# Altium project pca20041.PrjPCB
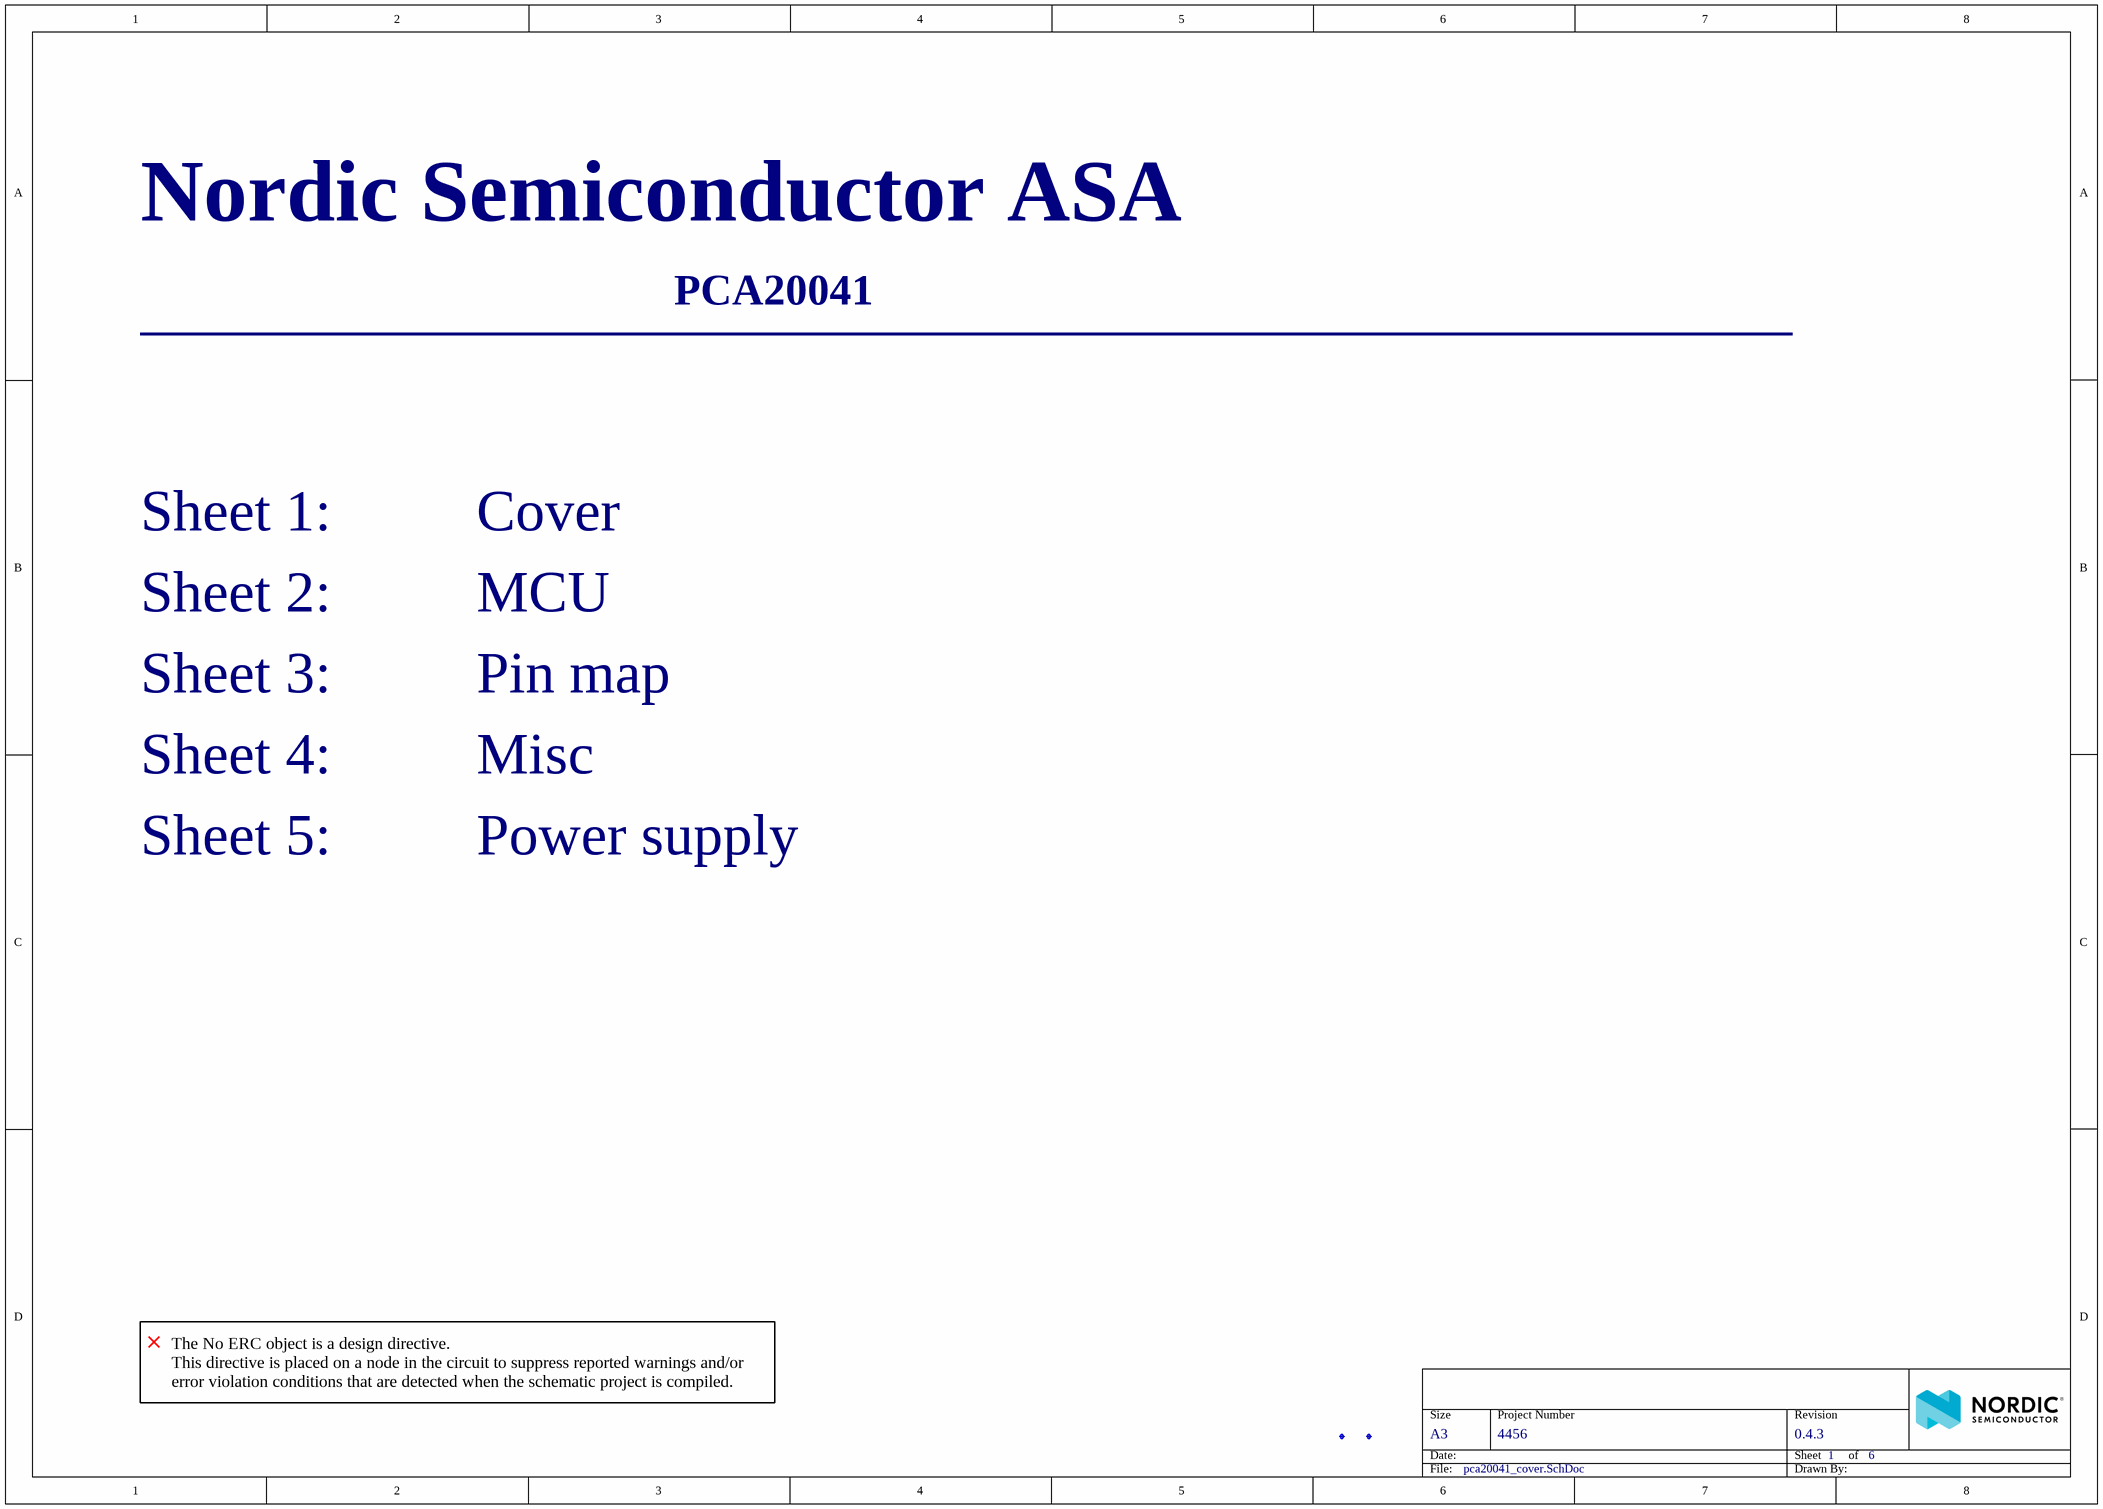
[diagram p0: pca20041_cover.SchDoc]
Author: RUBR/KJP/MASI; BoardThickness: 1.6mm; BoardTitle: nRF52840 Gaming Mouse; NrOfLayers: 4; Organization: Nordic Semiconductor; PCAName: PCA20041; PCBNumber: 400380; PCBRevision: 0012MASI; PCBStackup: 4001; ProjectName: nRF52 Desktop; ProjectNumber: 4456; Revision: 0.4.3; SilkscreenColor: White; SoldermaskColor: Blue; SurfaceFinish: ENIG
5 sheets, 122 parts. Net scope: flat (ports and power ports of the same name join across sheets).
Board file: 400380.PcbDoc
Sheets:
  pca20041_cover.SchDoc
  pca20041_mcu.SchDoc
  pca20041_pin_map.SchDoc
  pca20041_misc.SchDoc
  pca20041_power_supply.SchDoc

## Sheet pca20041_cover.SchDoc: =BoardTitle
size A3; Organization: Nordic Semiconductor; DocumentNumber: 1; Revision: 0.4.3; SheetNumber: 1; SheetTotal: 6; Author: RUBR/KJP/MASI; CompanyName: Nordic Semiconductor; DrawnBy: RUBR/KJP/MASI

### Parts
Fid1  Fiducial mark  [Fiducial]  (value not drawn)
Fid2  Fiducial mark  [Fiducial]  (value not drawn)

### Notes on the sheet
- Nordic Semiconductor ASA
- ________________________________________________________
- Sheet 1:          Cover
- Sheet 2:          MCU
- Sheet 3:          Pin map
- Sheet 4:          Misc
- Sheet 5:          Power supply
- The No ERC object is a design directive.
  This directive is placed on a node in the circuit to suppress reported warnings and/or error violation conditions that are detected when the schematic project is compiled.

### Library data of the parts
Fid1 Fid2 = Fid-Mark: Artikkelnr Noca: N.A.

## Sheet pca20041_mcu.SchDoc: =BoardTitle
size A3; Organization: Nordic Semiconductor; DocumentNumber: 2; Revision: 0.4.3; SheetNumber: 2; SheetTotal: 6; Author: RUBR/KJP/MASI; CompanyName: Nordic Semiconductor; DrawnBy: RUBR/KJP/MASI
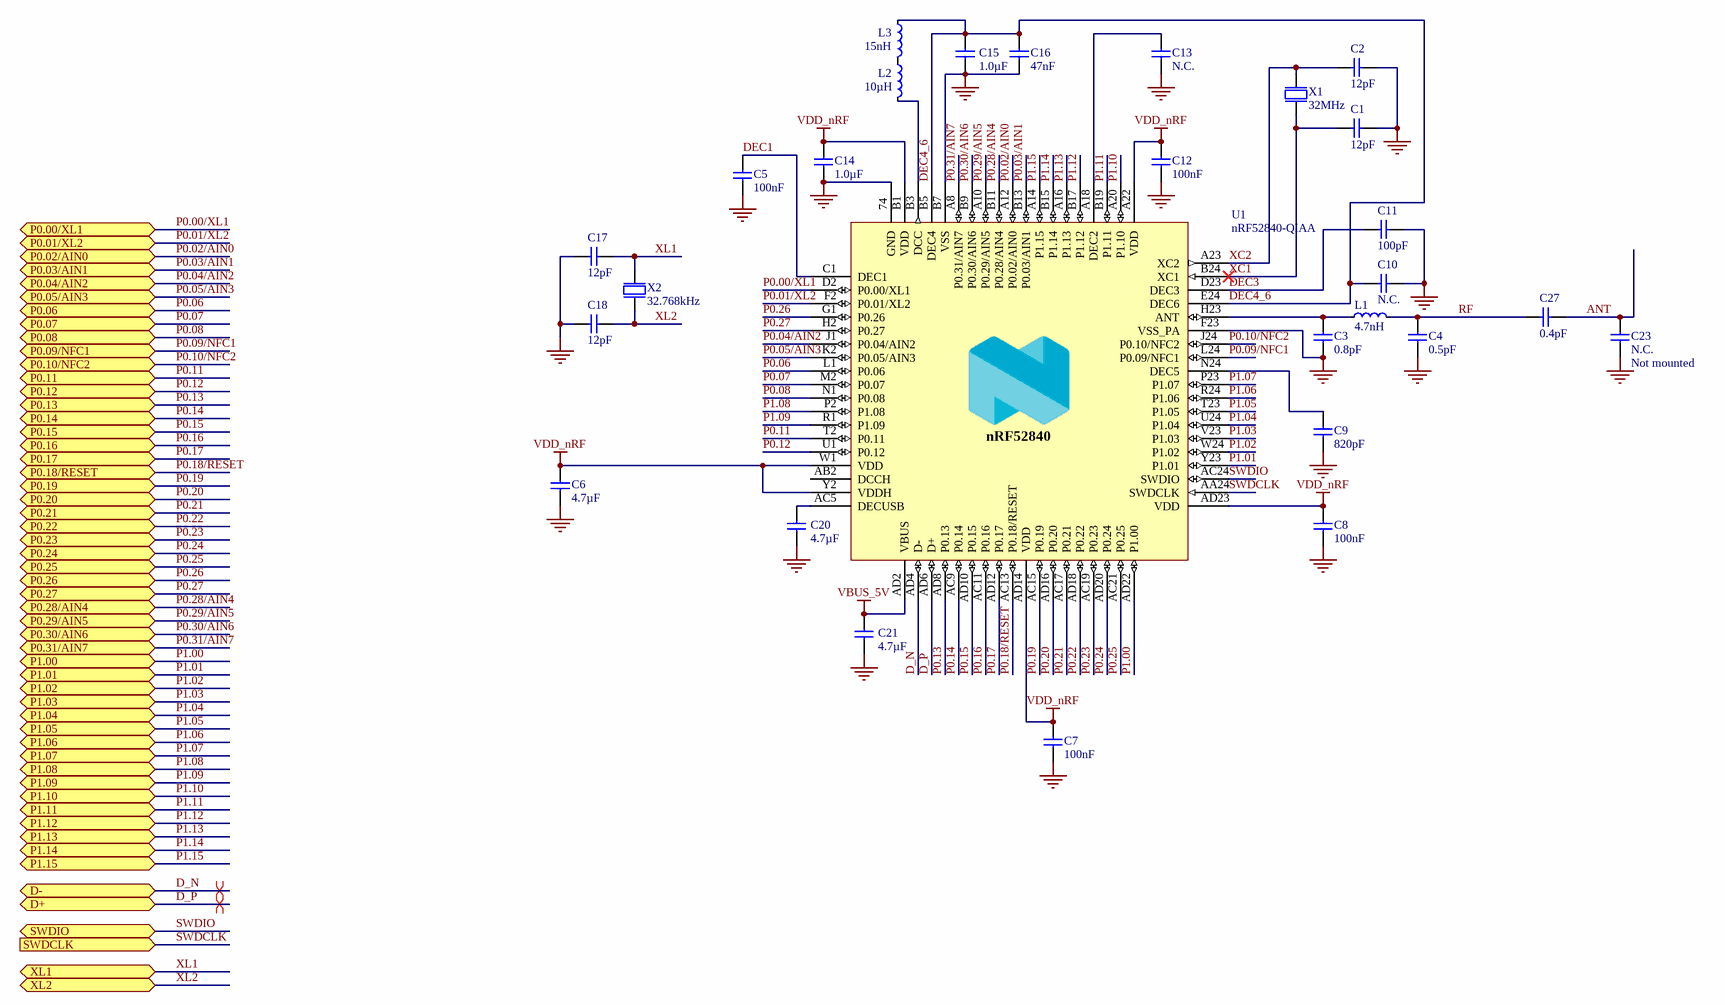
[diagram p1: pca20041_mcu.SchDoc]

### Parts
C1  12pF  [CAPC0603X03L_C]
C2  12pF  [CAPC0603X03L_C]
C3  0.8pF  [CAPC1005X04L]
C4  0.5pF  [CAPC1005X04L]
C5  100nF  [CAPC0603X03L_C]
C6  4.7µF  [CAPC1608X06L]
C7  100nF  [CAPC0603X03L_C]
C8  100nF  [CAPC0603X03L_C]
C9  820pF  [CAPC0603X03L_C]
C10  N.C.  [CAPC0603X03L_C]
C11  100pF  [CAPC0603X03L_C]
C12  100nF  [CAPC0603X03L_C]
C13  N.C.  [CAPC0603X03L_C]
C14  1.0µF  [CAPC1608X06L]
C15  1.0µF  [CAPC1608X06L]
C16  47nF  [CAPC0603X03L_C]
C17  12pF  [CAPC0603X03L_C]
C18  12pF  [CAPC0603X03L_C]
C20  4.7µF  [CAPC1608X06L]
C21  4.7µF  [CAPC1608X06L]
C23  N.C.  Assembly: Not mounted  [CAPC0603X03L_C]
C27  0.4pF  [CAPC0603X03L_C]
L1  4.7nH  [INDC1005X04L]
L2  10µH  [INDC1608X06L]
L3  15nH  [INDC1005X04L]
U1  nRF52840-QIAA  [AQFN50P700X700X85_HS-74N]
X1  32MHz  [BT-XTAL_2016]
X2  32.768kHz  [XTAL_2012]

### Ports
D+ (bidir), D- (bidir), P0.00/XL1 (bidir), P0.01/XL2 (bidir), P0.02/AIN0 (bidir), P0.03/AIN1 (bidir), P0.04/AIN2 (bidir), P0.05/AIN3 (bidir), P0.06 (bidir), P0.07 (bidir), P0.08 (bidir), P0.09/NFC1 (bidir), P0.10/NFC2 (bidir), P0.11 (bidir), P0.12 (bidir), P0.13 (bidir), P0.14 (bidir), P0.15 (bidir), P0.16 (bidir), P0.17 (bidir), P0.18/RESET (bidir), P0.19 (bidir), P0.20 (bidir), P0.21 (bidir), P0.22 (bidir), P0.23 (bidir), P0.24 (bidir), P0.25 (bidir), P0.26 (bidir), P0.27 (bidir), P0.28/AIN4 (bidir), P0.29/AIN5 (bidir), P0.30/AIN6 (bidir), P0.31/AIN7 (bidir), P1.00 (bidir), P1.01 (bidir), P1.02 (bidir), P1.03 (bidir), P1.04 (bidir), P1.05 (bidir), P1.06 (bidir), P1.07 (bidir), P1.08 (bidir), P1.09 (bidir), P1.10 (bidir), P1.11 (bidir), P1.12 (bidir), P1.13 (bidir), P1.14 (bidir), P1.15 (bidir), SWDCLK (in), SWDIO (bidir), XL1 (bidir), XL2 (bidir)

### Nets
GND: C1.2 C2.2 C3.1 C4.1 C5.2 C6.2 C7.2 C8.2 C9.2 C10.1 C11.2 C12.2 C13.2 C14.2 C15.1 C16.2 C17.2 C18.2 C20.2 C21.2 C23.2 U1.74(GND) U1.B7(VSS) U1.F23(VSS_PA) X1.2(GND) X1.4(GND)
VBUS_5V: C21.1 U1.AD2(VBUS)
VDD_nRF: C6.1 C7.1 C8.1 C12.1 C14.1 U1.A22(VDD) U1.AD14(VDD) U1.AD23(VDD) U1.B1(VDD) U1.W1(VDD) U1.Y2(VDDH)
ANT: C23.1 C27.2
D_N: U1.AD4(D-) ; port D-
D_P: U1.AD6(D+) ; port D+
DEC1: C5.1 U1.C1(DEC1)
DEC3: C11.1 U1.D23(DEC3)
DEC4_6: C10.2 C15.2 C16.1 L3.1 U1.B5(DEC4) U1.E24(DEC6)
P0.00/XL1: C17.1 U1.D2(P0.00/XL1) X2.1(inp) ; port P0.00/XL1, port XL1  [also labelled XL1]
P0.01/XL2: C18.1 U1.F2(P0.01/XL2) X2.2(out) ; port P0.01/XL2, port XL2  [also labelled XL2]
P0.02/AIN0: U1.A12(P0.02/AIN0) ; port P0.02/AIN0
P0.03/AIN1: U1.B13(P0.03/AIN1) ; port P0.03/AIN1
P0.04/AIN2: U1.J1(P0.04/AIN2) ; port P0.04/AIN2
P0.05/AIN3: U1.K2(P0.05/AIN3) ; port P0.05/AIN3
P0.06: U1.L1(P0.06) ; port P0.06
P0.07: U1.M2(P0.07) ; port P0.07
P0.08: U1.N1(P0.08) ; port P0.08
P0.09/NFC1: U1.L24(P0.09/NFC1) ; port P0.09/NFC1
P0.10/NFC2: U1.J24(P0.10/NFC2) ; port P0.10/NFC2
P0.11: U1.T2(P0.11) ; port P0.11
P0.12: U1.U1(P0.12) ; port P0.12
P0.13: U1.AD8(P0.13) ; port P0.13
P0.14: U1.AC9(P0.14) ; port P0.14
P0.15: U1.AD10(P0.15) ; port P0.15
P0.16: U1.AC11(P0.16) ; port P0.16
P0.17: U1.AD12(P0.17) ; port P0.17
P0.18/RESET: U1.AC13(P0.18/RESET) ; port P0.18/RESET
P0.19: U1.AC15(P0.19) ; port P0.19
P0.20: U1.AD16(P0.20) ; port P0.20
P0.21: U1.AC17(P0.21) ; port P0.21
P0.22: U1.AD18(P0.22) ; port P0.22
P0.23: U1.AC19(P0.23) ; port P0.23
P0.24: U1.AD20(P0.24) ; port P0.24
P0.25: U1.AC21(P0.25) ; port P0.25
P0.26: U1.G1(P0.26) ; port P0.26
P0.27: U1.H2(P0.27) ; port P0.27
P0.28/AIN4: U1.B11(P0.28/AIN4) ; port P0.28/AIN4
P0.29/AIN5: U1.A10(P0.29/AIN5) ; port P0.29/AIN5
P0.30/AIN6: U1.B9(P0.30/AIN6) ; port P0.30/AIN6
P0.31/AIN7: U1.A8(P0.31/AIN7) ; port P0.31/AIN7
P1.00: U1.AD22(P1.00) ; port P1.00
P1.01: U1.Y23(P1.01) ; port P1.01
P1.02: U1.W24(P1.02) ; port P1.02
P1.03: U1.V23(P1.03) ; port P1.03
P1.04: U1.U24(P1.04) ; port P1.04
P1.05: U1.T23(P1.05) ; port P1.05
P1.06: U1.R24(P1.06) ; port P1.06
P1.07: U1.P23(P1.07) ; port P1.07
P1.08: U1.P2(P1.08) ; port P1.08
P1.09: U1.R1(P1.09) ; port P1.09
P1.10: U1.A20(P1.10) ; port P1.10
P1.11: U1.B19(P1.11) ; port P1.11
P1.12: U1.B17(P1.12) ; port P1.12
P1.13: U1.A16(P1.13) ; port P1.13
P1.14: U1.B15(P1.14) ; port P1.14
P1.15: U1.A14(P1.15) ; port P1.15
RF: C4.2 C27.1 L1.2
SWDCLK: U1.AA24(SWDCLK) ; port SWDCLK
SWDIO: U1.AC24(SWDIO) ; port SWDIO
XC1: C1.1 U1.B24(XC1) X1.1(inp)
XC2: C2.1 U1.A23(XC2) X1.3(out)
NetC3_2: C3.2 L1.1 U1.H23(ANT)
NetC9_1: C9.1 U1.N24(DEC5)
NetC13_1: C13.1 U1.A18(DEC2)
NetC20_1: C20.1 U1.AC5(DECUSB)
NetL2_1: L2.1 L3.2
NetL2_2: L2.2 U1.B3(DCC)

Not connected (* = marked no-connect by the designer): U1 AB2(DCCH)

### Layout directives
differential pair: D_N, D_P

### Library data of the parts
C1 C2 C17 C18 = C0201-12p: Capacitor, NP0, ±2%; Part number IPS: 00000007848; Note: 25V; Artikkelnr Noca: N.A.
C3 = C0402-0.8p: Capacitor, NP0, ±5%; Part number IPS: 00000007782; Note: 50V; Artikkelnr Noca: 20029147
C4 = C0402-0.5p: Capacitor, NP0, ±0.05pF; Part number IPS: N.A.; Note: 50V; Artikkelnr Noca: 20020007
C5 C7 C8 C12 = C0201-100n: Capacitor, X5R, ±10%; Part number IPS: 00000001248; Note: 16V; Artikkelnr Noca: N.A.
C6 C20 = C0603-4µ7-6.3V-X7R: Capacitor, X7R, ±10%; Manufacturer: Samsung; Manufacturer Part Number: CL10B475KQ8NQNC; Part number IPS: N.A.; Note: 6.3V; Artikkelnr Noca: 20039473
C9 = C0201-820p: Capacitor, X7R, ±10%; Part number IPS: 00000001249; Note: 25V; Artikkelnr Noca: N.A.
C10 C13 = C0201-N.C.: Not mounted; Note: Chip Cap; Assembly: Not mounted; Artikkelnr Noca: N.A.
C11 = C0201-100p: Capacitor, NP0, ±2%; Part number IPS: 00000007853; Note: 25V; Artikkelnr Noca: N.A.
C14 C15 = C0603-1µ0: Capacitor, X7R, ±10%; Part number IPS: 00000000616; Note: 16V; Artikkelnr Noca: 20039282
C16 = C0201-47n: Capacitor, X5R, ±10%; Part number IPS: 00000001250; Note: 10V; Artikkelnr Noca: N.A.
C21 = C0603-4µ7-10V-X7S: Capacitor, X7S, ±10%; Part number IPS: N.A.; Note: 10V; Artikkelnr Noca: 20030013
C23 = C0201-N.C.: Not mounted; Note: Chip Cap; Artikkelnr Noca: N.A.
C27 = C0201-0.4p: Capacitor, NP0, ±0.05pF; Note: 50V; Artikkelnr Noca: N.A.
L1 = L0402-4n7: Inductor, 160mA, ±0.1nH; Manufacturer: Murata; Manufacturer Part Number: LQP15MN4N7B02D; Part number IPS: N.A.; Note: High frequency chip inductor ±5%; Artikkelnr Noca: 33029164
L2 = L0603-10µ: Inductor, 80mA, ±10%; Manufacturer: Taiyo Yuden; Manufacturer Part Number: LBMF1608T100K; Part number IPS: 00000007794; Note: LBMF1608T100K 10µH 80mA 0603; Artikkelnr Noca: 33029314
L3 = L0402-15n: Inductor, 320mA, ±5%; Manufacturer: Taiyo Yuden; Manufacturer Part Number: HK100515NJ-T; Part number IPS: 00000001262; Note: High frequency chip inductor ±10%; Artikkelnr Noca: 33029323
U1 = nRF52840-QIAAD0: Multi-protocol Bluetooth Low Energy, IEEE 802.15.4, ANT and 2.4GHz proprietary system-on-chip; Manufacturer: Nordic Semiconductor; Artikkelnr Noca: N.A.
X1 = XTAL_SMD2016_32MHz_8pF_General: XTAL SMD 2016, 32MHz, Cl=8pF, Total Tol: ±40ppm; Note: XTAL SMD 32.000MHz; Artikkelnr Noca: N.A.
X2 = XTAL_SMD2012_32.768kHz_9pF_NDK: XTAL SMD 2012, 32.768kHz, 9pF, ±20ppm; Manufacturer: NDK; Manufacturer Part Number: NX2012SA 32.768KHz  S1-4085-xx20-9; Note: XTAL SMD 32.768kHz; Artikkelnr Noca: N.A.

## Sheet pca20041_pin_map.SchDoc: =BoardTitle
size A3; Organization: Nordic Semiconductor; DocumentNumber: 3; Revision: 0.4.3; SheetNumber: 3; SheetTotal: 6; Author: RUBR/KJP/MASI; CompanyName: Nordic Semiconductor; DrawnBy: RUBR/KJP/MASI
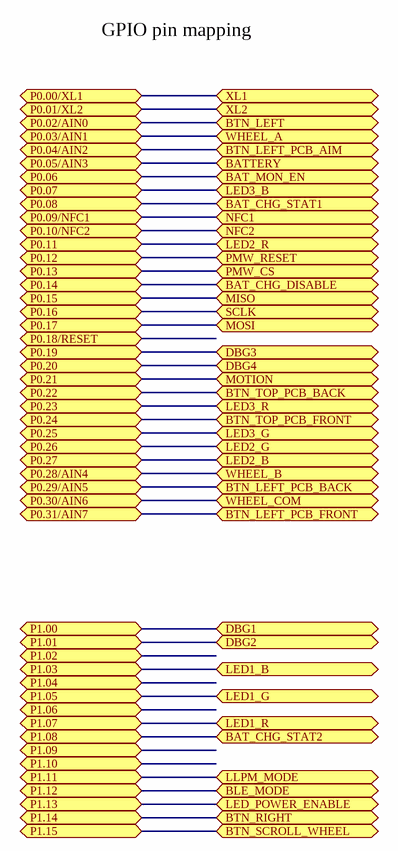
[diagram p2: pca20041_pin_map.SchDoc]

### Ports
BAT_CHG_DISABLE (bidir), BAT_CHG_STAT1 (bidir), BAT_CHG_STAT2 (bidir), BAT_MON_EN (bidir), BATTERY (bidir), BLE_MODE (bidir), BTN_LEFT (bidir), BTN_LEFT_PCB_AIM (bidir), BTN_LEFT_PCB_BACK (bidir), BTN_LEFT_PCB_FRONT (bidir), BTN_RIGHT (bidir), BTN_SCROLL_WHEEL (bidir), BTN_TOP_PCB_BACK (bidir), BTN_TOP_PCB_FRONT (bidir), DBG1 (bidir), DBG2 (bidir), DBG3 (bidir), DBG4 (bidir), LED1_B (bidir), LED1_G (bidir), LED1_R (bidir), LED2_B (bidir), LED2_G (bidir), LED2_R (bidir), LED3_B (bidir), LED3_G (bidir), LED3_R (bidir), LED_POWER_ENABLE (bidir), LLPM_MODE (bidir), MISO (bidir), MOSI (bidir), MOTION (bidir), NFC1 (bidir), NFC2 (bidir), P0.00/XL1 (bidir), P0.01/XL2 (bidir), P0.02/AIN0 (bidir), P0.03/AIN1 (bidir), P0.04/AIN2 (bidir), P0.05/AIN3 (bidir), P0.06 (bidir), P0.07 (bidir), P0.08 (bidir), P0.09/NFC1 (bidir), P0.10/NFC2 (bidir), P0.11 (bidir), P0.12 (bidir), P0.13 (bidir), P0.14 (bidir), P0.15 (bidir), P0.16 (bidir), P0.17 (bidir), P0.18/RESET (bidir), P0.19 (bidir), P0.20 (bidir), P0.21 (bidir), P0.22 (bidir), P0.23 (bidir), P0.24 (bidir), P0.25 (bidir), P0.26 (bidir), P0.27 (bidir), P0.28/AIN4 (bidir), P0.29/AIN5 (bidir), P0.30/AIN6 (bidir), P0.31/AIN7 (bidir), P1.00 (bidir), P1.01 (bidir), P1.02 (bidir), P1.03 (bidir), P1.04 (bidir), P1.05 (bidir), P1.06 (bidir), P1.07 (bidir), P1.08 (bidir), P1.09 (bidir), P1.10 (bidir), P1.11 (bidir), P1.12 (bidir), P1.13 (bidir), P1.14 (bidir), P1.15 (bidir), PMW_CS (bidir), PMW_RESET (bidir), SCLK (bidir), WHEEL_A (bidir), WHEEL_B (bidir), WHEEL_COM (bidir), XL1 (bidir), XL2 (bidir)

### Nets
P0.00/XL1: port XL1, port P0.00/XL1
P0.01/XL2: port XL2, port P0.01/XL2
P0.02/AIN0: port P0.02/AIN0, port BTN_LEFT
P0.03/AIN1: port P0.03/AIN1, port WHEEL_A
P0.04/AIN2: port P0.04/AIN2, port BTN_LEFT_PCB_AIM
P0.05/AIN3: port P0.05/AIN3, port BATTERY
P0.06: port P0.06, port BAT_MON_EN
P0.07: port P0.07, port LED3_B
P0.08: port P0.08, port BAT_CHG_STAT1
P0.09/NFC1: port P0.09/NFC1, port NFC1
P0.10/NFC2: port P0.10/NFC2, port NFC2
P0.11: port P0.11, port LED2_R
P0.12: port P0.12, port PMW_RESET
P0.13: port P0.13, port PMW_CS
P0.14: port P0.14, port BAT_CHG_DISABLE
P0.15: port P0.15, port MISO
P0.16: port P0.16, port SCLK
P0.17: port P0.17, port MOSI
P0.19: port P0.19, port DBG3
P0.20: port P0.20, port DBG4
P0.21: port P0.21, port MOTION
P0.22: port P0.22, port BTN_TOP_PCB_BACK
P0.23: port P0.23, port LED3_R
P0.24: port P0.24, port BTN_TOP_PCB_FRONT
P0.25: port P0.25, port LED3_G
P0.26: port P0.26, port LED2_G
P0.27: port P0.27, port LED2_B
P0.28/AIN4: port P0.28/AIN4, port WHEEL_B
P0.29/AIN5: port P0.29/AIN5, port BTN_LEFT_PCB_BACK
P0.30/AIN6: port P0.30/AIN6, port WHEEL_COM
P0.31/AIN7: port P0.31/AIN7, port BTN_LEFT_PCB_FRONT
P1.00: port P1.00, port DBG1
P1.01: port P1.01, port DBG2
P1.03: port P1.03, port LED1_B
P1.05: port P1.05, port LED1_G
P1.07: port P1.07, port LED1_R
P1.08: port P1.08, port BAT_CHG_STAT2
P1.11: port P1.11, port LLPM_MODE
P1.12: port P1.12, port BLE_MODE
P1.13: port P1.13, port LED_POWER_ENABLE
P1.14: port P1.14, port BTN_RIGHT
P1.15: port P1.15, port BTN_SCROLL_WHEEL

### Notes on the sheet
- GPIO pin mapping

## Sheet pca20041_misc.SchDoc: =BoardTitle
size A3; Organization: Nordic Semiconductor; DocumentNumber: 5; Revision: 0.4.3; SheetNumber: 5; SheetTotal: 6; Author: RUBR/KJP/MASI; CompanyName: Nordic Semiconductor; DrawnBy: RUBR/KJP/MASI
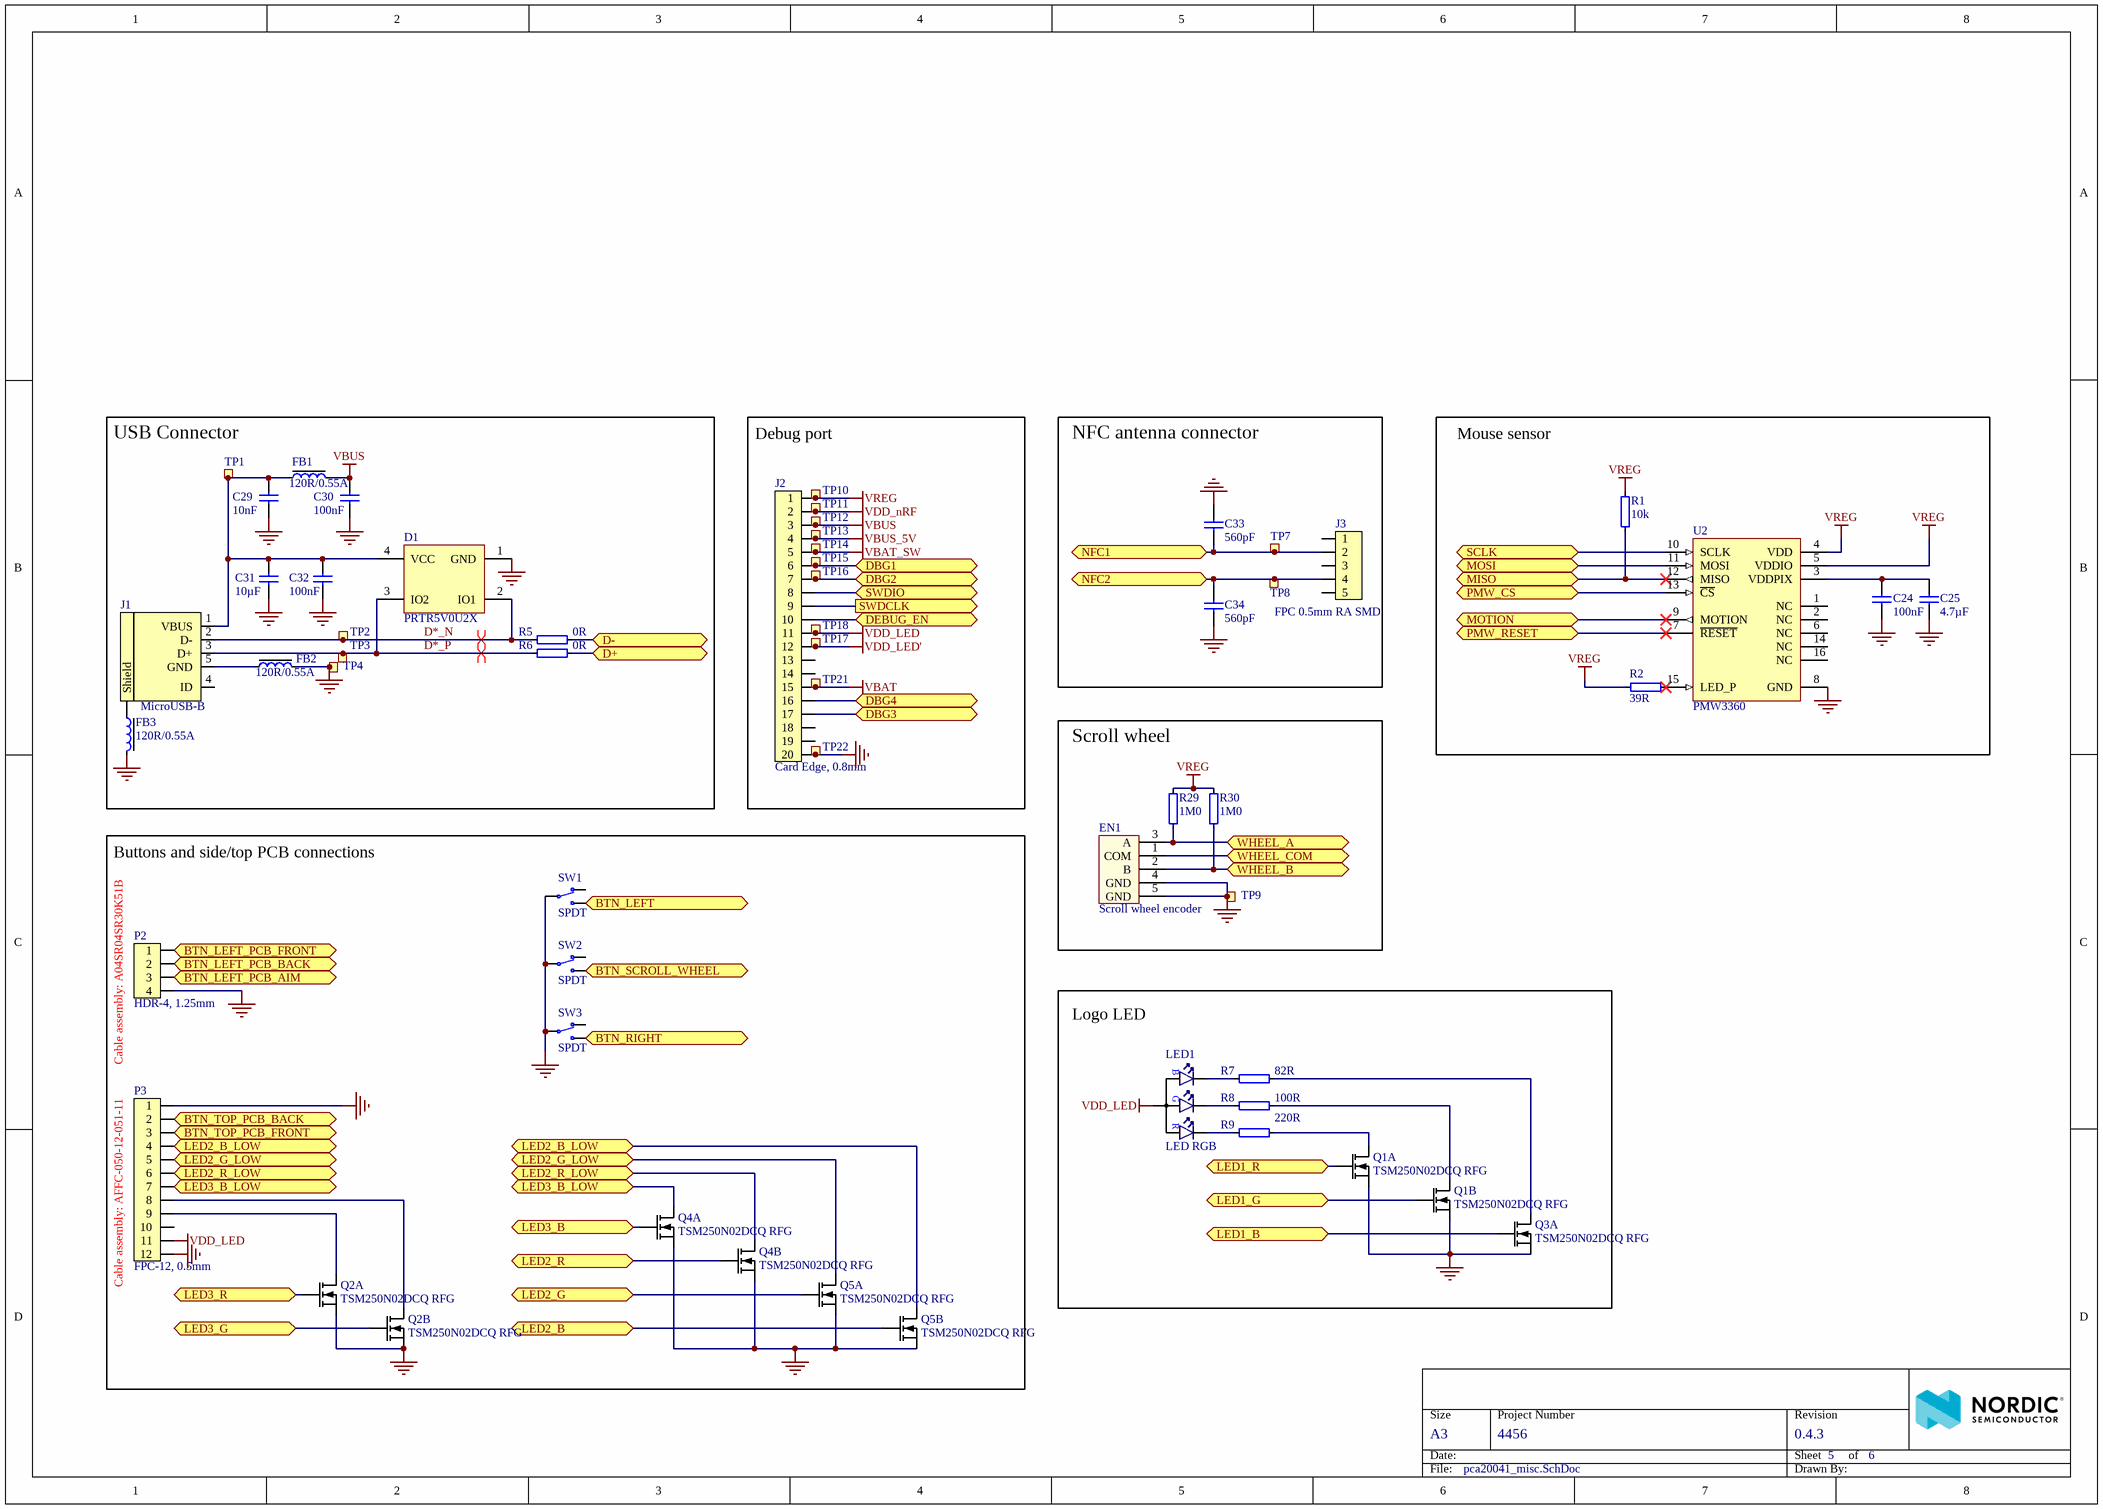
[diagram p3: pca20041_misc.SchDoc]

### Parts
C24  100nF  [CAPC1005X04L]
C25  4.7µF  [CAPC1608X06L]
C29  10nF  [CAPC1005X04L]
C30  100nF  [CAPC1005X04L]
C31  10µF  [CAPC1608X06L]
C32  100nF  [CAPC1005X04L]
C33  560pF  [CAPC1005X04L]
C34  560pF  [CAPC1005X04L]
D1  PRTR5V0U2X  [SOT190P230X110-4L]
EN1  Scroll wheel encoder  [M01_Scroll_Wheel_Encoder]
FB1  120R/0.55A  [INDC1005X04L]
FB2  120R/0.55A  [INDC1005X04L]
FB3  120R/0.55A  [INDC1005X04L]
J1  MicroUSB-B  [USB-Micro-B-RA-SMD-PiP]
J2  Card Edge, 0.8mm  [10056847-101LF]
J3  FPC 0.5mm RA SMD  [FPC_05P-0.5mm-RA-SMD]
LED1  LED RGB  [L1204_RGB_SIDE]
P2  HDR-4, 1.25mm  [1734598-4]
P3  FPC-12, 0.5mm  [10051922-1210ELF]
Q1  TSM250N02DCQ RFG  [DFN65P200X200X80_HS-6N]  (parts A,B of 2)
Q2  TSM250N02DCQ RFG  [DFN65P200X200X80_HS-6N]  (parts A,B of 2)
Q3  TSM250N02DCQ RFG  [DFN65P200X200X80_HS-6N]  (part A of 2)
Q4  TSM250N02DCQ RFG  [DFN65P200X200X80_HS-6N]  (parts A,B of 2)
Q5  TSM250N02DCQ RFG  [DFN65P200X200X80_HS-6N]  (parts A,B of 2)
R1  10k  [RESC0603X03L_C]
R2  39R  [RESC0603X03L_C]
R5  0R  [RESC0603X03L_C]
R6  0R  [RESC0603X03L_C]
R7  82R  [RESC0603X03L_C]
R8  100R  [RESC0603X03L_C]
R9  220R  [RESC0603X03L_C]
R29  1M0  [RESC0603X03L_C]
R30  1M0  [RESC0603X03L_C]
SW1  SPDT  [D2F-F]
SW2  SPDT  [D2F-F]
SW3  SPDT  [D2F-F]
TP1  Ø1.5mm,SMD  [TP_SMD_Ø1.5mm]  (value not drawn)  (no BOM)
TP2  Ø1.5mm,SMD  [TP_SMD_Ø1.5mm]  (value not drawn)  (no BOM)
TP3  Ø1.5mm,SMD  [TP_SMD_Ø1.5mm]  (value not drawn)  (no BOM)
TP4  Ø1.5mm,SMD  [TP_SMD_Ø1.5mm]  (value not drawn)  (no BOM)
TP7  Ø1.5mm,SMD  [TP_SMD_Ø1.5mm]  (value not drawn)  (no BOM)
TP8  Ø1.5mm,SMD  [TP_SMD_Ø1.5mm]  (value not drawn)  (no BOM)
TP9  TP  [TESTPAD-TH]  (value not drawn)  (no BOM)
TP10  Ø1.5mm,SMD  [TP_SMD_Ø1.5mm]  (value not drawn)  (no BOM)
TP11  Ø1.5mm,SMD  [TP_SMD_Ø1.5mm]  (value not drawn)  (no BOM)
TP12  Ø1.5mm,SMD  [TP_SMD_Ø1.5mm]  (value not drawn)  (no BOM)
TP13  Ø1.5mm,SMD  [TP_SMD_Ø1.5mm]  (value not drawn)  (no BOM)
TP14  Ø1.5mm,SMD  [TP_SMD_Ø1.5mm]  (value not drawn)  (no BOM)
TP15  Ø1.5mm,SMD  [TP_SMD_Ø1.5mm]  (value not drawn)  (no BOM)
TP16  Ø1.5mm,SMD  [TP_SMD_Ø1.5mm]  (value not drawn)  (no BOM)
TP17  Ø1.5mm,SMD  [TP_SMD_Ø1.5mm]  (value not drawn)  (no BOM)
TP18  Ø1.5mm,SMD  [TP_SMD_Ø1.5mm]  (value not drawn)  (no BOM)
TP21  Ø1.5mm,SMD  [TP_SMD_Ø1.5mm]  (value not drawn)  (no BOM)
TP22  Ø1.5mm,SMD  [TP_SMD_Ø1.5mm]  (value not drawn)  (no BOM)
U2  PMW3360  [PMW3360DM-T2QU]

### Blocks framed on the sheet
USB Connector: C29-C32 D1 FB1-FB3 J1 R5 R6 TP1-TP4
Debug port: J2 TP10-TP18 TP21 TP22
NFC antenna connector: C33 C34 J3 TP7 TP8
Mouse sensor: C24 C25 R1 R2 U2
Scroll wheel: EN1 R29 R30 TP9
Buttons and side/top PCB connections: P2 P3 Q2 Q4 Q5 SW1-SW3
Logo LED: LED1 Q1 Q3 R7-R9

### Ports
BTN_LEFT (bidir), BTN_LEFT_PCB_AIM (bidir), BTN_LEFT_PCB_BACK (bidir), BTN_LEFT_PCB_FRONT (bidir), BTN_RIGHT (bidir), BTN_SCROLL_WHEEL (bidir), BTN_TOP_PCB_BACK (bidir), BTN_TOP_PCB_FRONT (bidir), D+ (bidir), D- (bidir), DBG1 (bidir), DBG2 (bidir), DBG3 (bidir), DBG4 (bidir), DEBUG_EN (bidir), LED1_B (bidir), LED1_G (bidir), LED1_R (bidir), LED2_B (bidir), LED2_B_LOW (bidir), LED2_G (bidir), LED2_G_LOW (bidir), LED2_R (bidir), LED2_R_LOW (bidir), LED3_B (bidir), LED3_B_LOW (bidir), LED3_G (bidir), LED3_R (bidir), MISO (bidir), MOSI (bidir), MOTION (bidir), NFC1 (bidir), NFC2 (bidir), PMW_CS (bidir), PMW_RESET (bidir), SCLK (bidir), SWDCLK (out), SWDIO (bidir), WHEEL_A (bidir), WHEEL_B (bidir), WHEEL_COM (bidir)

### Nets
GND: C24.1 C25.1 C29.1 C30.1 C31.1 C32.1 C33.2 C34.1 D1.1(GND) EN1.4(GND) EN1.5(GND) FB2.2 FB3.2 J2.20 P2.4 P3.1 P3.12 Q1.1(S1) Q1.4(S2) Q2.1(S1) Q2.4(S2) Q3.1(S1) Q4.1(S1) Q4.4(S2) Q5.1(S1) Q5.4(S2) SW1.2(COM) SW2.2(COM) SW3.2(COM) TP4.1 TP9.1 TP22.1 U2.8(GND)
VBAT: J2.15 TP21.1
VBAT_SW: J2.5 TP14.1
VBUS: C30.2 FB1.2 J2.3 TP12.1
VBUS_5V: J2.4 TP13.1
VDD_LED: J2.11 LED1.4(A) P3.11 TP18.1
VDD_LED': J2.12 TP17.1
VDD_nRF: J2.2 TP11.1
VREG: J2.1 R1.2 R2.2 R29.2 R30.2 TP10.1 U2.4(VDD) U2.5(VDDIO)
D*_N: D1.2(IO1) J1.2(D-) R5.2 TP2.1
D*_P: D1.3(IO2) J1.3(D+) R6.2 TP3.1
D_N: R5.1 ; port D-
D_P: R6.1 ; port D+
EN: J2.10 ; port DEBUG_EN
LED2_B_LOW: P3.4 Q5.3(D2) ; port LED2_B_LOW
LED2_G_LOW: P3.5 Q5.6(D1) ; port LED2_G_LOW
LED2_R_LOW: P3.6 Q4.3(D2) ; port LED2_R_LOW
LED3_B_LOW: P3.7 Q4.6(D1) ; port LED3_B_LOW
P0.02/AIN0: SW1.3(N.O) ; port BTN_LEFT
P0.03/AIN1: EN1.3(A) R29.1 ; port WHEEL_A
P0.04/AIN2: P2.3 ; port BTN_LEFT_PCB_AIM
P0.07: Q4.2(G1) ; port LED3_B
P0.09/NFC1: C33.1 J3.2 TP7.1 ; port NFC1
P0.10/NFC2: C34.2 J3.4 TP8.1 ; port NFC2
P0.11: Q4.5(G2) ; port LED2_R
P0.12: U2.7(~{RESET}) ; port PMW_RESET
P0.13: U2.13(~{CS}) ; port PMW_CS
P0.15: R1.1 U2.12(MISO) ; port MISO
P0.16: U2.10(SCLK) ; port SCLK
P0.17: U2.11(MOSI) ; port MOSI
P0.19: J2.17 ; port DBG3
P0.20: J2.16 ; port DBG4
P0.21: U2.9(MOTION) ; port MOTION
P0.22: P3.2 ; port BTN_TOP_PCB_BACK
P0.23: Q2.2(G1) ; port LED3_R
P0.24: P3.3 ; port BTN_TOP_PCB_FRONT
P0.25: Q2.5(G2) ; port LED3_G
P0.26: Q5.2(G1) ; port LED2_G
P0.27: Q5.5(G2) ; port LED2_B
P0.28/AIN4: EN1.2(B) R30.1 ; port WHEEL_B
P0.29/AIN5: P2.2 ; port BTN_LEFT_PCB_BACK
P0.30/AIN6: EN1.1(COM) ; port WHEEL_COM
P0.31/AIN7: P2.1 ; port BTN_LEFT_PCB_FRONT
P1.00: J2.6 TP15.1 ; port DBG1
P1.01: J2.7 TP16.1 ; port DBG2
P1.03: Q3.2(G1) ; port LED1_B
P1.05: Q1.5(G2) ; port LED1_G
P1.07: Q1.2(G1) ; port LED1_R
P1.14: SW3.3(N.O) ; port BTN_RIGHT
P1.15: SW2.3(N.O) ; port BTN_SCROLL_WHEEL
SWDCLK: J2.9 ; port SWDCLK
SWDIO: J2.8 ; port SWDIO
NetC24_2: C24.2 C25.2 U2.3(VDDPIX)
NetC29_2: C29.2 C31.2 C32.2 D1.4(VCC) FB1.1 J1.1(VBUS) TP1.1
NetFB2_1: FB2.1 J1.5(GND)
NetFB3_1: FB3.1 J1.6(Shield)
NetLED1_1: LED1.1(C_RED) R9.2
NetLED1_2: LED1.2(C_GREEN) R8.2
NetLED1_3: LED1.3(C_BLUE) R7.2
NetP3_8: P3.8 Q2.3(D2)
NetP3_9: P3.9 Q2.6(D1)
NetQ1_3: Q1.3(D2) R8.1
NetQ1_6: Q1.6(D1) R9.1
NetQ3_6: Q3.6(D1) R7.1
NetR2_1: R2.1 U2.15(LED_P)

Not connected (* = marked no-connect by the designer): J1 4(ID); J2 13 14 18 19; J3 1 3 5; P3 10; SW1 1(N.C); SW2 1(N.C); SW3 1(N.C); U2 1(NC) 2(NC) 6(NC) 14(NC) 16(NC)

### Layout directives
differential pair: D*_N, D*_P

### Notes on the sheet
- Cable assembly: A04SR04SR30K51B
- (near P3) Cable assembly: AFFC-050-12-051-11

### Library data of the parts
C24 C30 C32 = C0402-100n: Capacitor, X7R, ±10%; Part number IPS: 00000005296; Note: 16V; Artikkelnr Noca: 20039200
C25 = C0603-4µ7: Capacitor, X5R, ±10%; Part number IPS: 00000007783; Note: 6.3V; Artikkelnr Noca: 20069060
C29 = C0402-10n: Capacitor, X7R, ±10%; Part number IPS: 00000007784; Note: 16V; Artikkelnr Noca: 20039166
C31 = C0603-10µ: Capacitor, X5R, ±20%; Part number IPS: 00000007785; Note: 6.3V; Artikkelnr Noca: 20039234
C33 C34 = C0402-560p: Capacitor, NP0, ±5%; Part number IPS: N.A.; Note: 50V; Artikkelnr Noca: 20029161
D1 = PRTR5V0U2X: Ultra low capacitance double rail-to-rail ESD protection diode; Manufacturer: NXP; Part number IPS: 00000009951; Artikkelnr Noca: 10069015
EN1 = M01_Scroll_wheel_encoder, 10.5mm: Scroll wheel encoder, 10.5mm; Artikkelnr Noca: N.A.
FB1-FB3 = FB0402-120R@100M-500mA: Ferrite Bead, 120 Ohm @ 100MHz, 500mA, 250 mOhm Max; Manufacturer: Murata; Manufacturer Part Number: BLM15AG121SN1D; Part number IPS: N.A.; Note: Chip EMIFIL Inductor Type Chip Ferrite Bead; Artikkelnr Noca: 33029317
J1 = USB-Micro-B-RA-SMD-PiP: MicroUSB-B-SMT; Manufacturer: Allen Creations Corp.; Manufacturer Part Number: AJU55-BS2111-L; Part number IPS: 00000007790; Artikkelnr Noca: 55029020
J2 = 10056847-101LF: 0.8mm pitch, dual edge, right angle, SMD, card edge connector; Manufacturer: FCI; Artikkelnr Noca: N.A.
J3 = FPC_05P-0.5mm-RA-SMD: 0.5mm FPC, 5P,Right Angle SMT,Double Contact,H=1.2mm,White, Tin plated; Manufacturer: W-CON; Manufacturer Part Number: 5141-05RZDNWR01; Part number IPS: 00000007792; Artikkelnr Noca: 55010020
LED1 = Led_RGB_Side: Optek, Side mounted RGB 1204 SMD LED; Manufacturer Part Number: OVSRRGBCC3; Artikkelnr Noca: N.A.
P2 = 1734598-4: Connector Header Through Hole 4 position 0.049" (1.25mm); Manufacturer: TE Connectivity; Artikkelnr Noca: N.A.
P3 = 10051922-1210ELF: 0.5mm pitch, bottom side contact, side entry SMD FPC connector; Manufacturer: FCI; Artikkelnr Noca: N.A.
Q1-Q5 = TSM250N02DCQ RFG: Dual N Ch MOFET, 5.8A, 55mOhm max, 620mW; Manufacturer: Taiwan Semiconductor; Artikkelnr Noca: N.A.
R1 = R0201-10k: Resistor, ±1%, 0.05W; Part number IPS: 00000001255; Note: Chip Res 1%; Artikkelnr Noca: N.A.
R2 = R0201-39R: Resistor, ±1%, 0.05W; Note: Chip Res 1%; Artikkelnr Noca: N.A.
R5 R6 = R0201-0R: Resistor, ±5%, 0.05W; Part number IPS: 00000003245; Note: Chip Res 5%; Artikkelnr Noca: N.A.
R7 = R0201-82R: Resistor, ±1%, 0.05W; Note: Chip Res 1%; Artikkelnr Noca: N.A.
R8 = R0201-100: Resistor, ±1%, 0.05W; Note: Chip Res 1%; Artikkelnr Noca: N.A.
R9 = R0201-220: Resistor, ±1%, 0.05W; Part number IPS: 00000000863; Note: Chip Res 1%; Artikkelnr Noca: N.A.
R29 R30 = R0201-1M0: Resistor, ±1%, 0.05W; Note: Chip Res 1%; Artikkelnr Noca: N.A.
SW1-SW3 = D2F-F: SWITCH SNAP ACTION SPDT 1A 125V; Manufacturer: Omron; Artikkelnr Noca: N.A.
TP1-TP4 TP7 TP8 TP10-TP18 TP21 TP22 = TP_SMD_Ø1.5MM: 1.0mm circular SMD testpad; Manufacturer: Nordic Semiconductor; Artikkelnr Noca: N.A.
TP9 = Testpoint TH: Testpoint, through hole; Artikkelnr Noca: N.A.
U2 = PMW3360DM-T2QU: Optical Gaming Navigation Sensor; Manufacturer: PixArt; Artikkelnr Noca: N.A.

## Sheet pca20041_power_supply.SchDoc: =BoardTitle
size A3; Organization: Nordic Semiconductor; DocumentNumber: 6; Revision: 0.4.3; SheetNumber: 6; SheetTotal: 6; Author: RUBR/KJP/MASI; CompanyName: Nordic Semiconductor; DrawnBy: RUBR/KJP/MASI
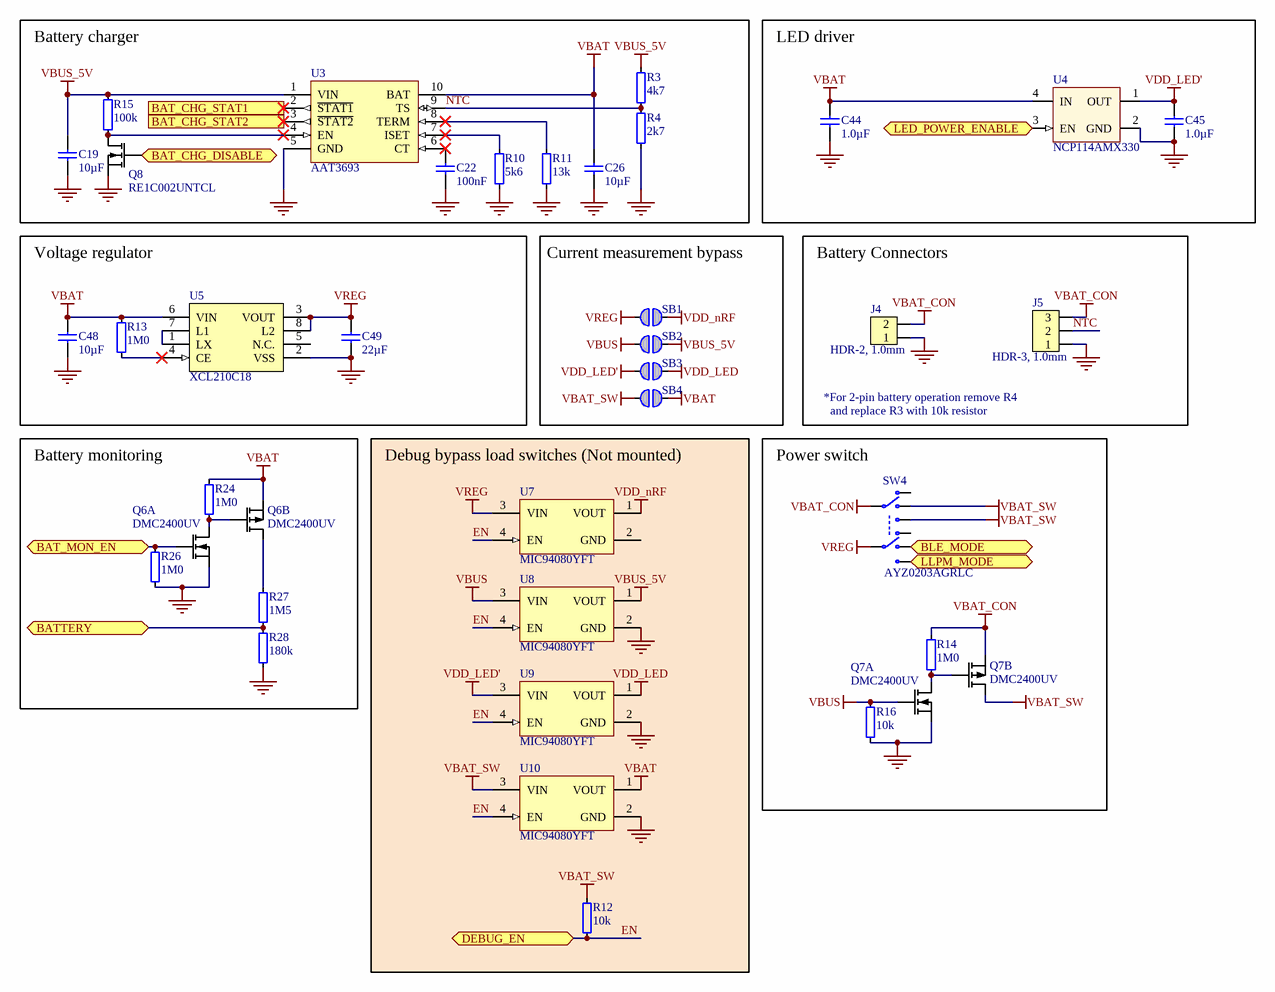
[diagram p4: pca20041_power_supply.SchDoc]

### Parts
C19  10µF  [CAPC1608X06L]
C22  100nF  [CAPC0603X03L_C]
C26  10µF  [CAPC1608X06L]
C44  1.0µF  [CAPC1005X04L]
C45  1.0µF  [CAPC1005X04L]
C48  10µF  [CAPC1608X06L]
C49  22µF  [CAPC1608X06L]
J4  HDR-2, 1.0mm  [BM02B-SRSS-TB]
J5  HDR-3, 1.0mm  [BM03B-SRSS-TB]
Q6  DMC2400UV  [SOTFL50P162X60-6N]  (parts A,B of 2)
Q7  DMC2400UV  [SOTFL50P162X60-6N]  (parts A,B of 2)
Q8  RE1C002UNTCL  [SOTFL50P160X78-3N]
R3  4k7  [RESC0603X03L_C]
R4  2k7  [RESC0603X03L_C]
R10  5k6  [RESC0603X03L_C]
R11  13k  [RESC0603X03L_C]
R12  10k  [RESC1005X04L]
R13  1M0  [RESC1005X04L]
R14  1M0  [RESC0603X03L_C]
R15  100k  [RESC0603X03L_C]
R16  10k  [RESC0603X03L_C]
R24  1M0  [RESC0603X03L_C]
R26  1M0  [RESC0603X03L_C]
R27  1M5  [RESC0603X03L_C]
R28  180k  [RESC0603X03L_C]
SB1  Solderbridge  [Solderbridge]  (value not drawn)  (no BOM)
SB2  Solderbridge  [Solderbridge]  (value not drawn)  (no BOM)
SB3  Solderbridge  [Solderbridge]  (value not drawn)  (no BOM)
SB4  Solderbridge  [Solderbridge]  (value not drawn)  (no BOM)
SW4  AYZ0203AGRLC  [AYZ0203AGRLC]
U3  AAT3693  [QFN40P220X220X80_HS-11N]
U4  NCP114AMX330  [UDFN65P100X100X60_HS-5N]
U5  XCL210C18  [CL-2025]
U7  MIC94080YFT  [TMLF40P85X85X60-4N]
U8  MIC94080YFT  [TMLF40P85X85X60-4N]
U9  MIC94080YFT  [TMLF40P85X85X60-4N]
U10  MIC94080YFT  [TMLF40P85X85X60-4N]

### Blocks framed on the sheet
Battery charger: C19 C22 C26 Q8 R3 R4 R10 R11 R15 U3
LED driver: C44 C45 U4
Voltage regulator: C48 C49 R13 U5
Current measurement bypass: SB1-SB4
Battery Connectors: J4 J5
Battery monitoring: Q6 R24 R26-R28
Debug bypass load switches (Not mounted): R12 U7-U10
Power switch: Q7 R14 R16 SW4

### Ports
BAT_CHG_DISABLE (bidir), BAT_CHG_STAT1 (out), BAT_CHG_STAT2 (out), BAT_MON_EN (bidir), BATTERY (bidir), BLE_MODE (bidir), DEBUG_EN (bidir), LED_POWER_ENABLE (bidir), LLPM_MODE (bidir)

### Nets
GND: C19.1 C22.2 C26.1 C44.2 C45.2 C48.1 C49.1 J4.1 J5.1 Q6.1(S1) Q7.1(S1) Q8.2(S) R4.1 R10.1 R11.1 R16.1 R26.2 R28.2 U3.5(GND) U3.11(GND) U4.2(GND) U4.5(EPAD) U5.2(VSS) U5.9(VSS) U7.2(GND) U8.2(GND) U9.2(GND) U10.2(GND)
VBAT: C26.2 C44.1 C48.2 Q6.4(S2) R13.2 R24.1 SB4.2 U3.10(BAT) U4.4(IN) U5.6(VIN) U10.1(VOUT)
VBAT_CON: J4.2 J5.3 Q7.4(S2) R14.2 SW4.3(COM-1)
VBAT_SW: Q7.3(D2) R12.2 SB4.1 SW4.2(N.O-1) SW4.4(COM-1) U10.3(VIN)
VBUS: Q7.2(G1) R16.2 SB2.1 U8.3(VIN)
VBUS_5V: C19.2 R3.2 R15.2 SB2.2 U3.1(VIN) U8.1(VOUT)
VDD_LED: SB3.2 U9.1(VOUT)
VDD_LED': C45.1 SB3.1 U4.1(OUT) U9.3(VIN)
VDD_nRF: SB1.2 U7.1(VOUT)
VREG: C49.2 SB1.1 SW4.7(COM-2) U5.3(VOUT) U5.8(L2) U7.3(VIN)
EN: R12.1 U7.4(EN) U8.4(EN) U9.4(EN) U10.4(EN) ; port DEBUG_EN
NTC: J5.2 R3.1 R4.2 U3.9(TS)
P0.05/AIN3: R27.2 R28.1 ; port BATTERY
P0.06: Q6.2(G1) R26.1 ; port BAT_MON_EN
P0.08: U3.2(~{STAT1}) ; port BAT_CHG_STAT1
P0.14: Q8.1(G) ; port BAT_CHG_DISABLE
P1.08: U3.3(~{STAT2}) ; port BAT_CHG_STAT2
P1.11: SW4.8(COM-2) ; port LLPM_MODE
P1.12: SW4.6(N.O-2) ; port BLE_MODE
P1.13: U4.3(EN) ; port LED_POWER_ENABLE
NetC22_1: C22.1 U3.6(CT)
NetQ6_3: Q6.3(D2) R27.1
NetQ6_5: Q6.5(G2) Q6.6(D1) R24.2
NetQ7_5: Q7.5(G2) Q7.6(D1) R14.1
NetQ8_3: Q8.3(D) R15.1 U3.4(EN)
NetR10_2: R10.2 U3.7(ISET)
NetR11_2: R11.2 U3.8(TERM)
NetR13_1: R13.1 U5.4(CE)
NetU5_1: U5.1(LX) U5.7(L1)

Not connected (* = marked no-connect by the designer): SW4 1(N.C-1) 5(N.C-2); U5 5(N.C.)

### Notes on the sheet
- *For 2-pin battery operation remove R4
- and replace R3 with 10k resistor

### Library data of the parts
C19 C26 = C0603-10µF-25V: Capacitor, 0603, 25V, X5R; Part number IPS: N.A.; Artikkelnr Noca: 20039436
C22 = C0201-100n: as C5 on sheet pca20041_mcu
C44 C45 = C0402-1µ0: Capacitor, X5R, ±5%; Part number IPS: 00000007786; Note: 6.3V; Artikkelnr Noca: 20039235
C48 = C0603-10µ: as C31 on sheet pca20041_misc
C49 = C0603-22µ-6.3V: CAP CER 22UF 6.3V 20% X5R 0603; Manufacturer: Samsung; Manufacturer Part Number: CL10A226MQ8NRNC; Part number IPS: 00000007787; Artikkelnr Noca: N.A.
J4 = BM02B-SRSS-TB: 1.0mm pitch top entry SMD wire to board connector; Manufacturer: JST; Note: JST, Header; Artikkelnr Noca: N.A.
J5 = BM03B-SRSS-TB: 1.0mm pitch top entry SMD wire to board connector; Manufacturer: JST; Note: JST, Header; Artikkelnr Noca: N.A.
Q6 Q7 = DMC2400UV: Dual N & P Ch MOFET, 1.03A/0.7A, 480mOhm, 450mW; Manufacturer: Diodes Incorporated; Part number IPS: 00000007803; Note: Dual N & P Channel Digital FET; Artikkelnr Noca: N.A.
Q8 = RE1C002UNTCL: MOSFET N-CH 20V 0.2A EMT3; Manufacturer: Rohm Semiconductor; Artikkelnr Noca: N.A.
R3 = R0201-4k7: Resistor, ±1%, 0.05W; Note: Chip Res 1%; Artikkelnr Noca: N.A.
R4 = R0201-2k7: Resistor, ±1%, 0.05W; Note: Chip Res 1%; Artikkelnr Noca: N.A.
R10 = R0201-5k6: Resistor, ±1%, 0.05W; Note: Chip Res 1%; Artikkelnr Noca: N.A.
R11 = R0201-13k: Resistor, ±1%, 0.05W; Note: Chip Res 1%; Artikkelnr Noca: N.A.
R12 = R0402-10k: Not Mounted; Part number IPS: 00000002093; Assembly: Not Mounted; Note: Chip Res 1%; Artikkelnr Noca: 27049097
R13 = R0402-1M0: Resistor, ±1%, 0.063W; Part number IPS: 00000006807; Note: Chip Res 1%; Artikkelnr Noca: 27049145
R14 R24 R26 = R0201-1M0: as R29 on sheet pca20041_misc
R15 = R0201-100k: Resistor, ±1%, 0.05W; Part number IPS: 00000001419; Note: Chip Res 1%; Artikkelnr Noca: N.A.
R16 = R0201-10k: as R1 on sheet pca20041_misc
R27 = R0201-1M5: Resistor, ±1%, 0.05W; Note: Chip Res 1%; Artikkelnr Noca: N.A.
R28 = R0201-180k: Resistor, ±1%, 0.05W; Note: Chip Res 1%; Artikkelnr Noca: N.A.
SB1-SB4 = Solderbridge: Artikkelnr Noca: N.A.
SW4 = AYZ0203AGRLC: Slide Switch DP3T Surface Mount, 100mA, 12V; Manufacturer: C&K Components; Artikkelnr Noca: N.A.
U3 = AAT3693: 1.6 A Single-cell Li-Ion/Polymer Battery Charger; Manufacturer: Skyworks; Manufacturer Part Number: AAT3693IDH-AA-T1; Artikkelnr Noca: N.A.
U4 = NCP114AMX330TBG: 300 mA CMOS Low Dropout Regulator; Manufacturer: ON Semiconductor; Artikkelnr Noca: N.A.
U5 = XCL210C18: 1.8V 200MA INDUCTOR BUILT-IN PFM STEP; Manufacturer: Torex Semiconductor; Manufacturer Part Number: XCL210C181GR-G; Artikkelnr Noca: N.A.
U7-U10 = MIC94080YFT: Not Mounted; Manufacturer: Microchip; Assembly: Not Mounted; Artikkelnr Noca: N.A.

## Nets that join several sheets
GND: pca20041_mcu (26 pins), pca20041_misc (33 pins), pca20041_power_supply (28 pins)
VBAT: pca20041_misc (J2.15 TP21.1), pca20041_power_supply (11 pins)
VBAT_SW: pca20041_misc (J2.5 TP14.1), pca20041_power_supply (6 pins)
VBUS: pca20041_misc (C30.2 FB1.2 J2.3 TP12.1), pca20041_power_supply (Q7.2 R16.2 SB2.1 U8.3)
VBUS_5V: pca20041_mcu (C21.1 U1.AD2), pca20041_misc (J2.4 TP13.1), pca20041_power_supply (6 pins)
VDD_LED: pca20041_misc (J2.11 LED1.4 P3.11 TP18.1), pca20041_power_supply (SB3.2 U9.1)
VDD_LED': pca20041_misc (J2.12 TP17.1), pca20041_power_supply (C45.1 SB3.1 U4.1 U9.3)
VDD_nRF: pca20041_mcu (11 pins), pca20041_misc (J2.2 TP11.1), pca20041_power_supply (SB1.2 U7.1)
VREG: pca20041_misc (8 pins), pca20041_power_supply (6 pins)
D_N: pca20041_mcu (U1.AD4), pca20041_misc (R5.1)
D_P: pca20041_mcu (U1.AD6), pca20041_misc (R6.1)
EN: pca20041_misc (J2.10), pca20041_power_supply (5 pins)
P0.02/AIN0: pca20041_mcu (U1.A12), pca20041_misc (SW1.3)
P0.03/AIN1: pca20041_mcu (U1.B13), pca20041_misc (EN1.3 R29.1)
P0.04/AIN2: pca20041_mcu (U1.J1), pca20041_misc (P2.3)
P0.05/AIN3: pca20041_mcu (U1.K2), pca20041_power_supply (R27.2 R28.1)
P0.06: pca20041_mcu (U1.L1), pca20041_power_supply (Q6.2 R26.1)
P0.07: pca20041_mcu (U1.M2), pca20041_misc (Q4.2)
P0.08: pca20041_mcu (U1.N1), pca20041_power_supply (U3.2)
P0.09/NFC1: pca20041_mcu (U1.L24), pca20041_misc (C33.1 J3.2 TP7.1)
P0.10/NFC2: pca20041_mcu (U1.J24), pca20041_misc (C34.2 J3.4 TP8.1)
P0.11: pca20041_mcu (U1.T2), pca20041_misc (Q4.5)
P0.12: pca20041_mcu (U1.U1), pca20041_misc (U2.7)
P0.13: pca20041_mcu (U1.AD8), pca20041_misc (U2.13)
P0.14: pca20041_mcu (U1.AC9), pca20041_power_supply (Q8.1)
P0.15: pca20041_mcu (U1.AD10), pca20041_misc (R1.1 U2.12)
P0.16: pca20041_mcu (U1.AC11), pca20041_misc (U2.10)
P0.17: pca20041_mcu (U1.AD12), pca20041_misc (U2.11)
P0.19: pca20041_mcu (U1.AC15), pca20041_misc (J2.17)
P0.20: pca20041_mcu (U1.AD16), pca20041_misc (J2.16)
P0.21: pca20041_mcu (U1.AC17), pca20041_misc (U2.9)
P0.22: pca20041_mcu (U1.AD18), pca20041_misc (P3.2)
P0.23: pca20041_mcu (U1.AC19), pca20041_misc (Q2.2)
P0.24: pca20041_mcu (U1.AD20), pca20041_misc (P3.3)
P0.25: pca20041_mcu (U1.AC21), pca20041_misc (Q2.5)
P0.26: pca20041_mcu (U1.G1), pca20041_misc (Q5.2)
P0.27: pca20041_mcu (U1.H2), pca20041_misc (Q5.5)
P0.28/AIN4: pca20041_mcu (U1.B11), pca20041_misc (EN1.2 R30.1)
P0.29/AIN5: pca20041_mcu (U1.A10), pca20041_misc (P2.2)
P0.30/AIN6: pca20041_mcu (U1.B9), pca20041_misc (EN1.1)
P0.31/AIN7: pca20041_mcu (U1.A8), pca20041_misc (P2.1)
P1.00: pca20041_mcu (U1.AD22), pca20041_misc (J2.6 TP15.1)
P1.01: pca20041_mcu (U1.Y23), pca20041_misc (J2.7 TP16.1)
P1.03: pca20041_mcu (U1.V23), pca20041_misc (Q3.2)
P1.05: pca20041_mcu (U1.T23), pca20041_misc (Q1.5)
P1.07: pca20041_mcu (U1.P23), pca20041_misc (Q1.2)
P1.08: pca20041_mcu (U1.P2), pca20041_power_supply (U3.3)
P1.11: pca20041_mcu (U1.B19), pca20041_power_supply (SW4.8)
P1.12: pca20041_mcu (U1.B17), pca20041_power_supply (SW4.6)
P1.13: pca20041_mcu (U1.A16), pca20041_power_supply (U4.3)
P1.14: pca20041_mcu (U1.B15), pca20041_misc (SW3.3)
P1.15: pca20041_mcu (U1.A14), pca20041_misc (SW2.3)
SWDCLK: pca20041_mcu (U1.AA24), pca20041_misc (J2.9)
SWDIO: pca20041_mcu (U1.AC24), pca20041_misc (J2.8)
